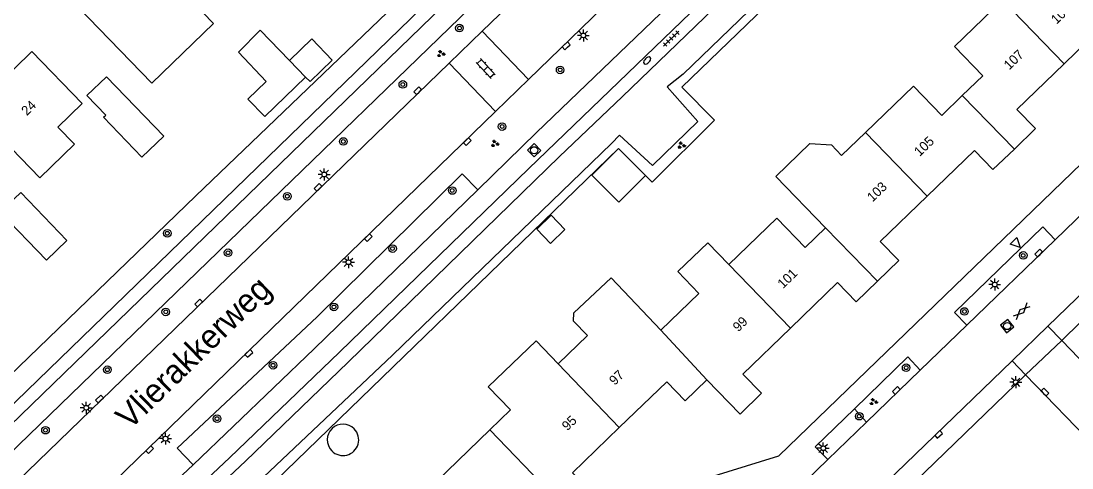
# Model space of a CAD drawing. Extents: x 137999 to 141000, y 397500 to 400501.
# Drawn here: x 138533.8 to 138644.2, y 399587.1 to 399634 of the extents above; entities that cross this region are included whole.
import ezdxf

# ---------------------------------------------------------------- set-up
doc = ezdxf.new("R2010")
doc.units = 0
for name, color, linetype in [('gg-afsc-erfafscheiding', 7, 'Continuous'), ('gg-anno-huisnummerreeks BGT', 7, 'Continuous'), ('gg-anno-openbare ruimte label', 7, 'Continuous'), ('gg-bbg-bijgebouw', 7, 'Continuous'), ('gg-bbg-gedigitaliseerde bebouwing', 7, 'Continuous'), ('gg-bbg-gedigitaliseerde bijgebouw', 7, 'Continuous'), ('gg-bbg-hoofdgebouw', 7, 'Continuous'), ('gg-bbg-tussenscheiding', 7, 'Continuous'), ('gg-knt-verharding', 7, 'Continuous'), ('gt-grn-groengrens', 7, 'Continuous'), ('gt-grn-weggrens', 7, 'Continuous'), ('gt-symb-boom', 7, 'Continuous'), ('gt-symb-brandkraan', 7, 'Continuous'), ('gt-symb-gesloten verharding', 7, 'Continuous'), ('gt-symb-groenvak', 7, 'Continuous'), ('gt-symb-klinker verharding', 7, 'Continuous'), ('gt-symb-kolk', 7, 'Continuous'), ('gt-symb-lichtmast', 7, 'Continuous'), ('gt-symb-rioolschacht', 7, 'Continuous'), ('gt-symb-tegel verharding', 7, 'Continuous'), ('gt-symb-waterafsluiter', 7, 'Continuous')]:
    doc.layers.add(name, color=color, linetype=linetype)

# ---------------------------------------------------------------- blocks, each defined once
blk = doc.blocks.new('gt0-BOOM')
at = {"layer": 'gt-symb-boom'}
for radius in [0.4, 0.2]:
    blk.add_circle((0, 0), radius, dxfattribs=at)
blk = doc.blocks.new('gt0-LMAST')
at = {"layer": 'gt-symb-lichtmast'}
for p, q in [((-0.18, 0.17), (-0.45, 0.44)), ((0, 0.25), (0, 0.62)), ((0.17, 0.17), (0.44, 0.44)), ((-0.25, 0), (-0.63, 0)), ((-0.18, -0.18), (-0.45, -0.45)), ((0, -0.25), (0, -0.63)), ((0.44, -0.45), (0.17, -0.18)), ((0.25, 0), (0.62, 0))]:
    blk.add_line(p, q, dxfattribs=at)
blk.add_circle((0, 0), 0.25, dxfattribs=at)
blk = doc.blocks.new('gt0-RS')
at = {"layer": 'gt-symb-rioolschacht'}
blk.add_lwpolyline([(-0.5, -0.5), (0.5, -0.5), (0.5, 0.5), (-0.5, 0.5)], close=True, dxfattribs=at)
blk.add_circle((0, 0), 0.375, dxfattribs=at)
blk = doc.blocks.new('gt0-WAFSL')
at = {"layer": 'gt-symb-waterafsluiter'}
for p, q in [((-0.5, -0.33), (0, 0.67)), ((0, 0.67), (0.5, -0.33)), ((0.5, -0.33), (-0.5, -0.33))]:
    blk.add_line(p, q, dxfattribs=at)
blk = doc.blocks.new('gt0-GESVH1')
at = {"layer": 'gt-symb-gesloten verharding'}
for p, q in [((-0.99, -0.26), (0.01, 0.24)), ((0.01, -0.26), (-0.99, 0.24)), ((0.01, 0.24), (1.01, -0.26)), ((1.01, 0.24), (0.01, -0.26))]:
    blk.add_line(p, q, dxfattribs=at)
blk = doc.blocks.new('gt0-KOLK')
at = {"layer": 'gt-symb-kolk'}
blk.add_lwpolyline([(0, 0), (0.37, 0), (0.37, 0.4), (-0.38, 0.4), (-0.38, 0), (0, 0)], dxfattribs=at)
blk = doc.blocks.new('gt0-GRVAK')
at = {"layer": 'gt-symb-groenvak'}
for p, q in [((-0.11, 0.19), (-0.23, 0.24)), ((-0.18, 0.15), (0.09, 0.15)), ((-0.09, 0.21), (-0.16, 0.32)), ((-0.05, 0.21), (-0.05, 0.39)), ((0, 0.21), (0.06, 0.32)), ((0.02, 0.19), (0.13, 0.24)), ((0.26, -0.05), (0.2, 0.06)), ((0.31, -0.05), (0.31, 0.13)), ((0.35, -0.05), (0.41, 0.06)), ((-0.24, -0.23), (-0.36, -0.18)), ((-0.32, -0.26), (-0.05, -0.26)), ((-0.23, -0.21), (-0.29, -0.09)), ((-0.18, -0.2), (-0.18, -0.02)), ((-0.14, -0.21), (-0.07, -0.09)), ((-0.12, -0.23), (0, -0.18)), ((0.24, -0.07), (0.12, -0.02)), ((0.17, -0.11), (0.44, -0.11)), ((0.37, -0.07), (0.49, -0.02))]:
    blk.add_line(p, q, dxfattribs=at)
blk = doc.blocks.new('gt0-TEG1')
at = {"layer": 'gt-symb-tegel verharding'}
for p, q in [((-1.13, 0), (1.12, 0)), ((-0.9, -0.25), (-0.9, 0.25)), ((-0.45, -0.25), (-0.45, 0.25)), ((0, -0.25), (0, 0.25)), ((0.45, -0.25), (0.45, 0.25)), ((0.9, -0.25), (0.9, 0.25))]:
    blk.add_line(p, q, dxfattribs=at)
blk = doc.blocks.new('gt0-KL1')
at = {"layer": 'gt-symb-klinker verharding'}
for p, q in [((-1.15, 0.3), (1.15, 0.3)), ((-1, -0.3), (-1, 0.3)), ((-0.5, 0.3), (-0.5, 0.45)), ((0, -0.3), (0, 0.3)), ((0.5, 0.3), (0.5, 0.45)), ((1, -0.3), (1, 0.3)), ((-1.15, -0.3), (1.15, -0.3)), ((-0.5, -0.45), (-0.5, -0.3)), ((0.5, -0.45), (0.5, -0.3))]:
    blk.add_line(p, q, dxfattribs=at)
blk = doc.blocks.new('gt0-BR')
at = {"layer": 'gt-symb-brandkraan'}
for centre, radius, start, end in [((-0.24, 0), 0.206, 107.5669, 252.4331), ((0.6, -2.66), 3, 106.892, 107.5669), ((0, -0.69), 0.938, 73.108, 106.892), ((-0.6, -2.66), 3, 72.4331, 73.108), ((0.24, 0), 0.206, 287.567, 72.4331), ((0.6, 2.66), 3, 252.4331, 253.108), ((0, 0.69), 0.938, 253.108, 286.8921), ((-0.6, 2.66), 3, 286.8921, 287.567)]:
    blk.add_arc(centre, radius, start, end, dxfattribs=at)

msp = doc.modelspace()

# ---------------------------------------------------------------- linework, layer by layer
at = {"layer": 'gg-afsc-erfafscheiding'}
for p, q in [((138632.53, 399655.42), (138603.24, 399627.06)), ((138596.59, 399620.62), (138546.07, 399571.73))]:
    msp.add_line(p, q, dxfattribs=at)
for points in [[(138530.43, 399594.73), (138552.14, 399615.67), (138590.69, 399652.6)], [(138599.4, 399617.8), (138600.11, 399617.09), (138606.67, 399623.61), (138603.24, 399627.06)]]:
    msp.add_lwpolyline(points, dxfattribs=at)
at = {"layer": 'gg-bbg-bijgebouw'}
for points in [[(138563.69, 399628.14), (138564.17, 399627.67), (138566.5, 399629.91), (138564.35, 399632.14)], [(138548.79, 399621.94), (138546.48, 399619.73), (138542.46, 399623.92), (138542.69, 399624.14), (138540.71, 399626.19), (138542.78, 399628.18), (138548.79, 399621.94)], [(138557.61, 399625.82), (138559.4, 399623.98), (138563.69, 399628.14)], [(138531.59, 399613.93), (138533.75, 399616.01), (138538.61, 399610.97), (138536.45, 399608.89), (138531.59, 399613.93)]]:
    msp.add_lwpolyline(points, dxfattribs=at)
at = {"layer": 'gg-bbg-gedigitaliseerde bebouwing'}
for p, q in [((138622.53, 399622.32), (138620.02, 399619.9)), ((138605.02, 399605.4), (138601.01, 399601.54)), ((138593.3, 399600.97), (138590.24, 399598.02)), ((138585.21, 399593.17), (138583.05, 399591.09)), ((138583.05, 399591.09), (138575.87, 399584.14))]:
    msp.add_line(p, q, dxfattribs=at)
for points in [[(138539.75, 399635.53), (138547.55, 399627.48), (138554.02, 399633.76), (138546.22, 399641.81)], [(138636.92, 399636.22), (138631.89, 399631.36), (138634.86, 399628.28), (138632.7, 399626.19)], [(138534.94, 399630.82), (138540.23, 399625.36), (138537.66, 399622.87), (138539.4, 399621.08), (138535.77, 399617.56), (138528.74, 399624.81)], [(138632.7, 399626.19), (138630.54, 399624.11), (138627.57, 399627.18), (138622.53, 399622.32)], [(138618.34, 399612.31), (138613.09, 399617.7), (138616.67, 399621.15), (138618.94, 399621.02), (138620.02, 399619.9)], [(138618.34, 399612.31), (138616.18, 399610.22), (138613.2, 399613.3), (138608.16, 399608.44)], [(138608.16, 399608.44), (138605.95, 399610.74), (138602.8, 399607.71), (138605.02, 399605.4)], [(138593.3, 399600.97), (138591.84, 399602.48), (138591.88, 399603.37), (138595.79, 399607.06), (138601.01, 399601.54)], [(138590.24, 399598.02), (138587.91, 399600.43), (138582.89, 399595.58), (138585.21, 399593.17)]]:
    msp.add_lwpolyline(points, dxfattribs=at)
at = {"layer": 'gg-bbg-gedigitaliseerde bijgebouw'}
for p, q in [((138564.35, 399632.14), (138562, 399629.88)), ((138596.59, 399620.62), (138599.4, 399617.8))]:
    msp.add_line(p, q, dxfattribs=at)
for points in [[(138562, 399629.88), (138558.93, 399633.07), (138556.63, 399630.76), (138559.55, 399627.67), (138557.61, 399625.82)], [(138596.59, 399620.62), (138593.78, 399617.83), (138596.6, 399615.01), (138599.4, 399617.8)], [(138589.49, 399613.62), (138590.95, 399612.11), (138589.44, 399610.65), (138587.98, 399612.16), (138589.49, 399613.62)]]:
    msp.add_lwpolyline(points, dxfattribs=at)
for start, end in [(44.1398, 224.1398), (224.1398, 44.1398)]:
    msp.add_arc((138567.62, 399590.02), 1.65, start, end, dxfattribs=at)
at = {"layer": 'gg-bbg-hoofdgebouw'}
msp.add_line((138534.94, 399630.82), (138528.74, 399624.81), dxfattribs=at)
for points in [[(138643.39, 399629.53), (138648.34, 399634.31), (138650.29, 399632.3), (138652.53, 399634.47), (138647.15, 399640.02), (138647.08, 399640.09), (138644.93, 399638.01), (138641.95, 399641.08)], [(138643.39, 399629.53), (138638.43, 399624.74), (138640.41, 399622.74), (138638.17, 399620.58)], [(138638.17, 399620.58), (138635.92, 399618.42), (138633.97, 399620.43), (138629.01, 399615.64)], [(138629.01, 399615.64), (138624.07, 399610.86), (138626.02, 399608.85), (138623.79, 399606.7)], [(138623.79, 399606.7), (138621.55, 399604.53), (138619.6, 399606.55), (138614.65, 399601.76)], [(138614.65, 399601.76), (138609.65, 399596.93), (138611.61, 399594.93), (138609.35, 399592.72), (138605.87, 399596.32)], [(138605.87, 399596.32), (138603.59, 399594.11), (138601.65, 399596.11), (138596.66, 399591.31)], [(138596.66, 399591.31), (138591.73, 399586.57), (138593.68, 399584.55), (138591.43, 399582.38)]]:
    msp.add_lwpolyline(points, dxfattribs=at)
at = {"layer": 'gg-bbg-tussenscheiding'}
for p, q in [((138636.92, 399636.22), (138643.39, 399629.53)), ((138563.69, 399628.14), (138562, 399629.88)), ((138632.7, 399626.19), (138638.17, 399620.58)), ((138629.01, 399615.64), (138622.53, 399622.32)), ((138618.34, 399612.31), (138623.79, 399606.7)), ((138608.16, 399608.44), (138614.65, 399601.76)), ((138605.87, 399596.32), (138601.01, 399601.54)), ((138590.24, 399598.02), (138596.66, 399591.31)), ((138583.05, 399591.09), (138591.43, 399582.38))]:
    msp.add_line(p, q, dxfattribs=at)
at = {"layer": 'gg-knt-verharding'}
for p, q in [((138619.83, 399669.35), (138582.26, 399632.97)), ((138587.1, 399627.88), (138624.59, 399664.24)), ((138607.06, 399660.7), (138527.9, 399584.03)), ((138627.95, 399660.74), (138587.97, 399622.3)), ((138592.79, 399651.81), (138532.13, 399592.97)), ((138582.26, 399632.97), (138578.77, 399629.6)), ((138587.1, 399627.88), (138582.26, 399632.97)), ((138578.77, 399629.6), (138529.74, 399582.13)), ((138583.64, 399624.53), (138578.77, 399629.6)), ((138583.64, 399624.53), (138587.1, 399627.88)), ((138536.16, 399578.47), (138583.64, 399624.53)), ((138587.97, 399622.3), (138581.78, 399616.29)), ((138647.36, 399615.79), (138642.46, 399611.05)), ((138641.69, 399601.97), (138653.16, 399613.05)), ((138642.46, 399611.05), (138633.17, 399602.07)), ((138633.17, 399602.07), (138628.28, 399597.34)), ((138641.69, 399601.97), (138637.94, 399598.34)), ((138641.69, 399601.97), (138643.16, 399600.45)), ((138643.16, 399600.45), (138645.13, 399602.39)), ((138643.16, 399600.45), (138655.82, 399587.27)), ((138596.43, 399558.24), (138637.94, 399598.34)), ((138639.35, 399596.87), (138637.94, 399598.34)), ((138628.28, 399597.34), (138622.64, 399591.89)), ((138639.35, 399596.87), (138597.85, 399556.77)), ((138639.35, 399596.87), (138706.18, 399527.42)), ((138622.64, 399591.89), (138618.56, 399587.95)), ((138618.56, 399587.95), (138613.62, 399583.18))]:
    msp.add_line(p, q, dxfattribs=at)
for points in [[(138681.8, 399709.62), (138629.68, 399659.49), (138587.15, 399618.54)], [(138508.51, 399568.99), (138511.68, 399571.45), (138513.23, 399572.77), (138620.21, 399676.41)], [(138590.38, 399619.79), (138596.95, 399626.07), (138630.64, 399658.55), (138631.84, 399659.68)], [(138586.09, 399568.91), (138602.76, 399585.05), (138613.43, 399588.35), (138658.61, 399631.98), (138655.13, 399635.58)], [(138541.41, 399573.02), (138546.39, 399577.46), (138557.36, 399587.79), (138568.18, 399598.19), (138590.38, 399619.79)], [(138518.94, 399554.11), (138532.08, 399566.44), (138537.99, 399571.86), (138542.52, 399575.82), (138546.21, 399579.2), (138555.69, 399588.13), (138567.26, 399599.22), (138587.15, 399618.54)], [(138581.78, 399616.29), (138564.6, 399599.6), (138551.88, 399587.41)], [(138633.17, 399602.07), (138631.88, 399603.42), (138641.18, 399612.42), (138642.46, 399611.05)], [(138621.39, 399593.3), (138626.97, 399598.73), (138628.28, 399597.34)], [(138618.56, 399587.95), (138617.25, 399589.29), (138621.39, 399593.3)], [(138551.88, 399587.41), (138550.77, 399586.34), (138542.38, 399578.5), (138538.97, 399575.45)]]:
    msp.add_lwpolyline(points, dxfattribs=at)
at = {"layer": 'gt-grn-groengrens'}
msp.add_line((138621.39, 399593.3), (138622.64, 399591.89), dxfattribs=at)
for points in [[(138603.37, 399628.45), (138615.18, 399639.86), (138633.63, 399657.83)], [(138603.37, 399628.45), (138601.67, 399627.1), (138604.91, 399623.47), (138600.14, 399618.84), (138596.67, 399622.03), (138595.84, 399621.17)], [(138545.12, 399572.74), (138572.83, 399598.93), (138595.84, 399621.17)], [(138581.78, 399616.29), (138580.15, 399617.96), (138564.91, 399602.96), (138550.2, 399589.16), (138551.88, 399587.41)]]:
    msp.add_lwpolyline(points, dxfattribs=at)
at = {"layer": 'gt-grn-weggrens'}
msp.add_line((138639.35, 399596.87), (138643.16, 399600.45), dxfattribs=at)

# ---------------------------------------------------------------- block references
at = {"layer": 'gt-symb-boom'}
for p in [(138579.86, 399633.29), (138590.44, 399628.89), (138573.91, 399627.36), (138584.34, 399622.94), (138567.65, 399621.37), (138561.77, 399615.61), (138579.1, 399616.22), (138549.16, 399611.73), (138572.83, 399610.12), (138555.54, 399609.68), (138639.1, 399609.4), (138549, 399603.47), (138566.67, 399603.99), (138632.93, 399603.51), (138560.27, 399597.86), (138542.86, 399597.39), (138626.8, 399597.6), (138554.39, 399592.25), (138621.87, 399592.51), (138536.36, 399591.04)]:
    msp.add_blockref('gt0-BOOM', p, dxfattribs=at)
at = {"layer": 'gt-symb-brandkraan', "rotation": 44.189646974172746}
msp.add_blockref('gt0-BR', (138599.59, 399629.88), dxfattribs=at)
at = {"layer": 'gt-symb-gesloten verharding', "rotation": 43.54158234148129}
msp.add_blockref('gt0-GESVH1', (138638.93, 399603.54), dxfattribs=at)
at = {"layer": 'gt-symb-groenvak'}
for p in [(138577.9, 399630.58), (138583.57, 399621.14), (138603.18, 399620.97), (138623.36, 399594.02)]:
    msp.add_blockref('gt0-GRVAK', p, dxfattribs=at)
at = {"layer": 'gt-symb-klinker verharding', "rotation": 132.44710185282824}
msp.add_blockref('gt0-KL1', (138582.63, 399629.03), dxfattribs=at)
at = {"layer": 'gt-symb-kolk'}
for p, rotation in [((138591.22, 399631.28), 44.10862414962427), ((138575.61, 399626.56), 44.10862415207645), ((138580.83, 399621.22), 44.10862414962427), ((138565.13, 399616.41), 44.10862415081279), ((138570.42, 399611.12), 44.10862414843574), ((138640.87, 399609.51), 44.02760489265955), ((138552.59, 399604.26), 44.10862414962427), ((138557.87, 399598.96), 44.10862414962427), ((138625.92, 399595.07), 44.02760489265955), ((138641.24, 399594.91), -46.13442163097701), ((138542.18, 399594.18), 44.10862414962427), ((138630.35, 399590.45), 44.02760489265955), ((138547.45, 399588.86), 44.10862414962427)]:
    msp.add_blockref('gt0-KOLK', p, dxfattribs=dict(at, rotation=rotation))
at = {"layer": 'gt-symb-lichtmast'}
for p in [(138592.88, 399632.51), (138565.65, 399617.9), (138568.2, 399608.68), (138636.11, 399606.34), (138638.32, 399596.08), (138540.64, 399593.4), (138548.97, 399590.15), (138618.09, 399589.14)]:
    msp.add_blockref('gt0-LMAST', p, dxfattribs=at)
at = {"layer": 'gt-symb-rioolschacht'}
for p, rotation in [((138587.71, 399620.45), 133.9465895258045), ((138637.42, 399601.98), 38.62400399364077)]:
    msp.add_blockref('gt0-RS', p, dxfattribs=dict(at, rotation=rotation))
at = {"layer": 'gt-symb-tegel verharding', "rotation": 44.02760489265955}
msp.add_blockref('gt0-TEG1', (138602.11, 399632.18), dxfattribs=at)
at = {"layer": 'gt-symb-waterafsluiter', "rotation": -135.97239510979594}
msp.add_blockref('gt0-WAFSL', (138638.31, 399610.71), dxfattribs=at)

# ---------------------------------------------------------------- texts
at = {"layer": 'gg-anno-huisnummerreeks BGT'}
for s, rotation, p in [('109', 44, (138642.6, 399633.63)), ('107', 44, (138637.64, 399628.84)), ('24', 44.1, (138534.4, 399624.03)), ('105', 44, (138628.22, 399619.74)), ('103', 44, (138623.27, 399614.96)), ('101', 44, (138613.86, 399605.86)), ('99', 44, (138609.16, 399601.32)), ('97', 43.9, (138596.17, 399595.7)), ('95', 43.9, (138591.2, 399590.92))]:
    msp.add_text(s, height=1, rotation=rotation, dxfattribs=at).set_placement(p)
at = {"layer": 'gg-anno-openbare ruimte label'}
msp.add_text('Vlierakkerweg', height=2.5, rotation=44.2, dxfattribs=at).set_placement((138545.22, 399591))

doc.saveas('drawing.dxf')
